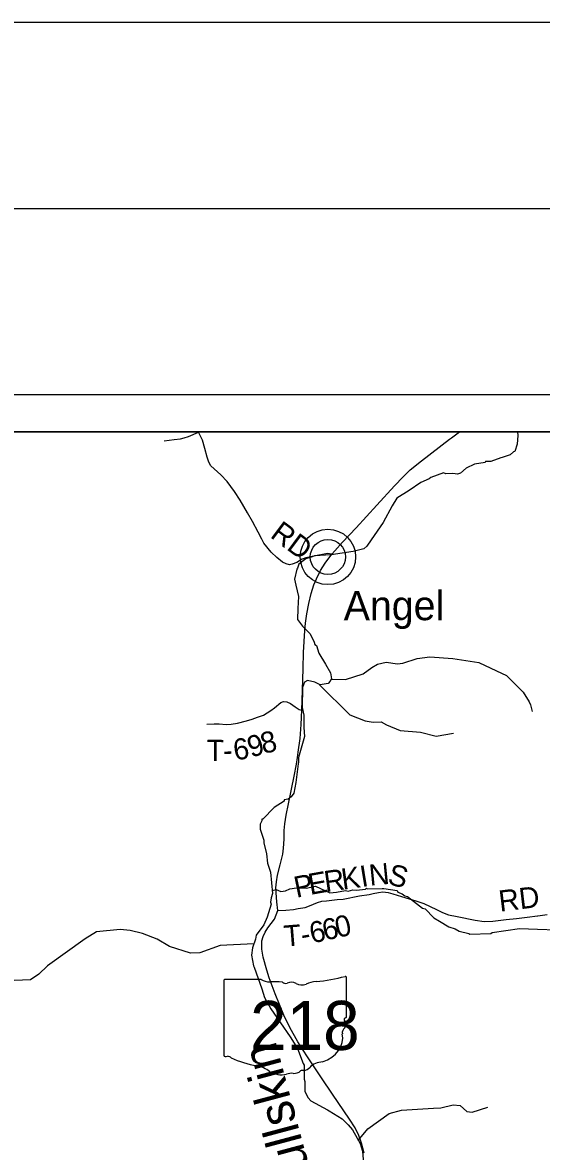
# Model space of a CAD drawing. Extents: x -1.8 to 75.7, y -2 to 25.
# Drawn here: x 46.551 to 47.944, y 20.577 to 23.612 of the extents above; entities that cross this region are included whole.
import ezdxf

# ---------------------------------------------------------------- set-up
doc = ezdxf.new("R2010")
doc.units = 0
for name, color, linetype in [('GM_X_County_Road', 7, 'Continuous'), ('GM_X_County_Road_Text', 7, 'Continuous'), ('GM_X_Minor_River', 7, 'Continuous'), ('GM_X_Minor_River_Text', 7, 'Continuous'), ('GM_X_State_Location', 7, 'Continuous'), ('GM_X_State_Route', 7, 'Continuous'), ('GM_X_State_Shield', 7, 'Continuous'), ('GM_X_Township', 7, 'Continuous'), ('GM_X_Township_Road', 7, 'Continuous'), ('GM_X_Township_Road_Text', 7, 'Continuous'), ('GM_X_Unincorporated', 7, 'Continuous'), ('GM_X_Unincorporated_Location', 7, 'Continuous'), ('GM_X_Unincorporated_Text', 7, 'Continuous'), ('SH_Border', 7, 'Continuous'), ('SH_Cut_Line', 7, 'Continuous'), ('SH_Data', 7, 'Continuous')]:
    doc.layers.add(name, color=color, linetype=linetype)

msp = doc.modelspace()

# ---------------------------------------------------------------- linework, layer by layer
at = {"layer": 'GM_X_County_Road'}
msp.add_lwpolyline([(47.3812, 22.183), (47.3696, 22.185), (47.3328, 22.1778), (47.311, 22.1729), (47.301, 22.1692), (47.2869, 22.1609), (47.2746, 22.156), (47.2669, 22.1545), (47.2588, 22.1566), (47.2482, 22.1614), (47.2333, 22.1738), (47.2178, 22.1881), (47.1983, 22.2125), (47.1926, 22.2231), (47.1834, 22.2418), (47.1676, 22.271), (47.1547, 22.2943), (47.1346, 22.3278), (47.1194, 22.3516), (47.0996, 22.3783), (47.083, 22.3964), (47.0646, 22.4124), (47.056, 22.4205), (47.0508, 22.4299), (47.046, 22.4434), (47.0397, 22.4672), (47.0336, 22.489), (47.0233, 22.5108), (47.0227, 22.5121)], dxfattribs=at)
at = {"layer": 'GM_X_Minor_River'}
for points in [[(47.8797, 22.5121), (47.8808, 22.502), (47.8785, 22.4788), (47.8729, 22.4587), (47.8687, 22.4583), (47.86, 22.4503), (47.8385, 22.443), (47.8347, 22.4422), (47.8079, 22.4319), (47.7935, 22.4322), (47.7931, 22.4296), (47.7644, 22.4253), (47.7417, 22.4139), (47.7266, 22.4009), (47.7187, 22.3979), (47.7062, 22.3997), (47.6873, 22.3989), (47.6813, 22.4012), (47.6469, 22.3893), (47.642, 22.3859), (47.62, 22.376), (47.5883, 22.3542), (47.5558, 22.3336), (47.543, 22.3131), (47.5192, 22.2682), (47.4871, 22.2213), (47.4754, 22.2042), (47.4671, 22.1973), (47.4384, 22.1897), (47.3794, 22.1816), (47.3348, 22.1788), (47.3284, 22.1761), (47.311, 22.17), (47.2925, 22.1563), (47.2887, 22.1456), (47.2872, 22.1426), (47.2808, 22.1156), (47.2846, 22.0992), (47.2911, 22.0692), (47.2896, 22.0369), (47.2892, 22.0069), (47.3025, 21.9894), (47.3225, 21.9689), (47.3339, 21.9462), (47.3354, 21.9401), (47.3396, 21.9378), (47.3464, 21.9166), (47.3642, 21.8873), (47.3778, 21.8638), (47.3801, 21.8482), (47.3775, 21.844), (47.3763, 21.8417), (47.3711, 21.8349), (47.3495, 21.8314), (47.3355, 21.8386), (47.3155, 21.8435), (47.3075, 21.8389), (47.3026, 21.8241), (47.3012, 21.7705), (47.3057, 21.75), (47.3058, 21.7173), (47.3073, 21.6926), (47.3043, 21.6804), (47.2911, 21.6367), (47.2915, 21.6234), (47.2904, 21.6196), (47.2844, 21.569), (47.2791, 21.5401), (47.2715, 21.5309), (47.264, 21.5241), (47.2534, 21.5222), (47.253, 21.5191), (47.2262, 21.502), (47.196, 21.4707), (47.1926, 21.4703), (47.1926, 21.4661), (47.1888, 21.4574), (47.1885, 21.4437), (47.1983, 21.4145), (47.198, 21.4072), (47.2059, 21.3772), (47.2086, 21.3522), (47.2162, 21.3278), (47.2215, 21.2708), (47.2181, 21.2594), (47.2159, 21.2473), (47.2178, 21.2419), (47.2076, 21.2073), (47.1982, 21.1864), (47.1782, 21.159)], [(47.379, 21.8471), (47.4179, 21.8458), (47.4656, 21.8614), (47.4884, 21.8785), (47.5038, 21.8875), (47.5267, 21.8929), (47.5575, 21.8881), (47.5715, 21.8895), (47.6105, 21.9027), (47.6443, 21.9066), (47.7057, 21.9027), (47.7757, 21.8914), (47.8234, 21.8697), (47.8503, 21.8567), (47.895, 21.8124), (47.9109, 21.786), (47.9148, 21.7783), (47.9188, 21.7596)], [(47.3483, 21.832), (47.4298, 21.751), (47.4709, 21.7349), (47.492, 21.7312), (47.5139, 21.732), (47.528, 21.7243), (47.5646, 21.7087), (47.6193, 21.7043), (47.6613, 21.6939), (47.7077, 21.7015)], [(47.2207, 21.2792), (47.2313, 21.2811), (47.2438, 21.2762), (47.2563, 21.2778), (47.268, 21.2831), (47.2862, 21.2862), (47.3119, 21.2847), (47.3368, 21.2901), (47.3758, 21.2727), (47.3939, 21.2747), (47.4173, 21.2789), (47.4249, 21.277), (47.437, 21.2808), (47.4476, 21.2797), (47.4714, 21.2824), (47.4744, 21.2851), (47.4763, 21.2828), (47.5164, 21.2837), (47.5209, 21.2841), (47.5568, 21.2788), (47.558, 21.2747), (47.5701, 21.2701), (47.5769, 21.2641), (47.5844, 21.2629), (47.6249, 21.2315), (47.6313, 21.2296), (47.6548, 21.2053), (47.6699, 21.1959), (47.6949, 21.1807), (47.7123, 21.1758), (47.7233, 21.1694), (47.7493, 21.163), (47.7516, 21.1615), (47.8076, 21.1635), (47.8113, 21.1662), (47.8847, 21.177), (47.9334, 21.1752), (47.9845, 21.1734)], [(47.1715, 21.1353), (47.0815, 21.1308), (47.0262, 21.1108), (47.0011, 21.1099), (46.9449, 21.1286), (46.9121, 21.1478), (46.8729, 21.1635), (46.8395, 21.1713), (46.8129, 21.1735), (46.7492, 21.1678), (46.7182, 21.149), (46.6173, 21.0764), (46.5939, 21.0542), (46.5716, 21.0389), (46.5287, 21.0368), (46.4638, 21.0418), (46.407, 21.0156), (46.3964, 21.0107), (46.3945, 21.0103)], [(47.1782, 21.159), (47.1759, 21.148), (47.1676, 21.1244), (47.165, 21.105), (47.1711, 21.0765), (47.1722, 21.0723), (47.193, 21.0146), (47.2003, 20.991), (47.2169, 20.9606), (47.2695, 20.8851), (47.2892, 20.8544), (47.3044, 20.8141), (47.307, 20.8092), (47.3071, 20.7715), (47.3083, 20.7651)], [(47.3083, 20.7654), (47.3086, 20.7385), (47.3173, 20.7214), (47.3249, 20.713), (47.3695, 20.6888), (47.3737, 20.6862), (47.4092, 20.6653), (47.4251, 20.649), (47.4365, 20.635), (47.4569, 20.5986), (47.4634, 20.5784), (47.4676, 20.5233)], [(47.4521, 20.6071), (47.4776, 20.6378), (47.5348, 20.6793), (47.568, 20.6885), (47.6543, 20.6937), (47.674, 20.6946), (47.7067, 20.7027), (47.7256, 20.7006), (47.7436, 20.6848), (47.7575, 20.6828), (47.8003, 20.6963)]]:
    msp.add_lwpolyline(points, dxfattribs=at)
at = {"layer": 'GM_X_State_Route'}
for points in [[(47.3812, 22.183), (47.3894, 22.192), (47.4101, 22.2148), (47.4463, 22.2535), (47.5022, 22.3146), (47.5497, 22.3663), (47.5725, 22.3908), (47.5916, 22.41), (47.6216, 22.4343), (47.6972, 22.4917), (47.7025, 22.4956)], [(47.7025, 22.4956), (47.7242, 22.5121)], [(47.2886, 21.6363), (47.291, 21.6508), (47.2961, 21.6878), (47.2987, 21.7248), (47.3004, 21.7638), (47.3019, 21.8175), (47.3041, 21.876), (47.3053, 21.919), (47.3082, 21.9775), (47.3107, 21.9971), (47.3139, 22.0229), (47.3191, 22.0504), (47.3251, 22.0774), (47.3328, 22.1003), (47.34, 22.1164), (47.3509, 22.1391), (47.3635, 22.1589), (47.3812, 22.183)], [(47.4679, 20.5727), (47.4604, 20.5999), (47.4531, 20.6198), (47.4436, 20.6405), (47.4285, 20.6643), (47.3829, 20.7309), (47.3535, 20.7748), (47.3138, 20.8341), (47.2893, 20.8722), (47.2679, 20.9107), (47.2521, 20.9435), (47.2288, 21.0008), (47.2125, 21.0441), (47.2062, 21.0643), (47.1967, 21.0995), (47.1928, 21.1214), (47.1931, 21.1432), (47.1965, 21.1554), (47.2016, 21.1671), (47.2089, 21.1782), (47.2271, 21.2018), (47.2319, 21.2132), (47.2356, 21.2254), (47.2336, 21.2486), (47.2313, 21.2721), (47.231, 21.2859), (47.2321, 21.3023), (47.2353, 21.32), (47.2422, 21.3476), (47.2491, 21.3766), (47.2511, 21.3929), (47.2528, 21.4167), (47.2531, 21.4402), (47.2548, 21.4583), (47.2588, 21.4813), (47.2648, 21.5117), (47.2798, 21.5863), (47.2858, 21.6187), (47.2886, 21.6363)]]:
    msp.add_lwpolyline(points, dxfattribs=at)
at = {"layer": 'GM_X_State_Shield'}
for p, q in [((47.0912, 21.0362), (47.0912, 20.8361)), ((47.1909, 21.0396), (47.0944, 21.0396)), ((47.4208, 20.9399), (47.4208, 21.0446)), ((47.4207, 20.9399), (47.4208, 20.9399))]:
    msp.add_line(p, q, dxfattribs=at)
for centre, major_axis, start_param, end_param in [((47.0949, 21.0366), (0.00382, 0), 1.712693, 3.28349), ((47.2139, 21.0628), (0.037, 0), 4.042523, 4.731795), ((47.2262, 20.9273), (0.133, 0), 1.404758, 1.657858), ((47.2564, 21.0376), (0.0107, 0), 3.836095, 5.185415), ((47.2721, 21.0145), (0.0222, 0), 0.950623, 2.079405), ((47.3479, 20.9785), (0.0703, 0), 1.699011, 2.107814), ((47.3034, 21.3124), (0.3495, 0), 4.814394, 5.042369), ((47.4171, 21.045), (0.00367, 0), 6.141152, 7.989035), ((47.3007, 21.0462), (0.0267, 0), 4.081561, 5.145723), ((47.4339, 20.8961), (0.0248, 0), 2.387724, 3.262537), ((47.4199, 20.9322), (0.00568, 0), 1.883978, 3.671073), ((47.3838, 20.919), (0.0341, 0), 5.934695, 6.695948), ((47.4168, 20.9395), (0.00393, 0), 5.05454, 6.418171), ((47.3229, 20.8828), (0.0874, 0), 5.101752, 6.440018), ((47.095, 20.8356), (0.00385, 0), 3.00124, 4.508301), ((47.0956, 20.8561), (0.0294, 0), 4.665946, 4.897461), ((47.1016, 20.8245), (0.0106, 0), 0.519207, 1.627899), ((47.2354, 21.0043), (0.2524, 0), 4.195997, 4.488961), ((47.1602, 20.7461), (0.079, 0), 0.823519, 1.323587), ((47.2456, 20.8235), (0.0501, 0), 4.026481, 4.996735), ((47.2782, 20.8085), (0.0267, 0), 4.691044, 5.507374), ((47.3023, 20.7891), (0.00752, 0), 1.147584, 2.315152), ((47.2991, 20.8167), (0.0282, 0), 4.937069, 5.64225), ((47.3598, 20.7799), (0.0479, 0), 1.647645, 2.488434), ((47.2745, 20.7543), (0.0412, 0), 1.495662, 1.94098)]:
    msp.add_ellipse(centre, major_axis=major_axis, ratio=0.8, start_param=start_param, end_param=end_param, dxfattribs=at)
at = {"layer": 'GM_X_Township'}
msp.add_lwpolyline([(48.1876, 22.5121), (43.8002, 22.5121), (43.8002, 18.978)], dxfattribs=at)
at = {"layer": 'GM_X_Township_Road'}
for points in [[(46.9304, 22.4873), (46.9579, 22.491), (46.9742, 22.4933), (46.9846, 22.4954), (46.9958, 22.4991), (47.0233, 22.5108)], [(47.0451, 21.726), (47.0649, 21.7265), (47.0781, 21.7268), (47.0973, 21.7254), (47.1105, 21.726), (47.1274, 21.7283), (47.1521, 21.7346), (47.1667, 21.7392), (47.1817, 21.7446), (47.1977, 21.7503), (47.2172, 21.763), (47.2267, 21.7701), (47.2445, 21.7842), (47.2516, 21.7868), (47.2603, 21.7859), (47.2697, 21.7816), (47.2829, 21.7721), (47.293, 21.765), (47.3004, 21.7638)], [(47.2356, 21.2254), (47.2575, 21.226), (47.2779, 21.2279), (47.2907, 21.2302), (47.3093, 21.2329), (47.3214, 21.2374), (47.3426, 21.2463), (47.3541, 21.2505), (47.3669, 21.2514), (47.3954, 21.2544), (47.4116, 21.2553), (47.4551, 21.2642), (47.4817, 21.2681), (47.4923, 21.2704), (47.5065, 21.2737), (47.5182, 21.2754), (47.5319, 21.2734), (47.5453, 21.2698), (47.5802, 21.2589), (47.6062, 21.2508), (47.628, 21.2438), (47.6617, 21.2274), (47.6779, 21.2193), (47.6944, 21.2134), (47.7173, 21.2089), (47.7664, 21.1994), (47.7899, 21.1958), (47.8133, 21.1964), (47.8491, 21.2008), (47.8767, 21.2036), (47.9052, 21.2073), (47.933, 21.2107)], [(47.933, 21.2107), (47.9345, 21.2109), (47.9597, 21.2138)]]:
    msp.add_lwpolyline(points, dxfattribs=at)
at = {"layer": 'GM_X_Unincorporated'}
for radius in [0.0744, 0.0472]:
    msp.add_circle((47.3704, 22.1756), radius, dxfattribs=at)
at = {"layer": 'GM_X_Unincorporated_Location'}
msp.add_line((47.3704, 22.1756), (47.3704, 22.1756), dxfattribs=at)
at = {"layer": 'SH_Border'}
msp.add_lwpolyline([(43.2002, 23.1121), (75.2002, 23.1121), (75.2002, 2.1121), (43.2002, 2.1121)], close=True, dxfattribs=at)
at = {"layer": 'SH_Cut_Line'}
msp.add_lwpolyline([(41.7002, 1.6121), (75.7002, 1.6121), (75.7002, 23.6121), (41.7002, 23.6121)], close=True, dxfattribs=at)
at = {"layer": 'SH_Data'}
for p, q in [((43.7002, 22.6121), (50.7002, 22.6121)), ((43.8002, 22.5121), (50.6002, 22.5121)), ((43.8002, 22.5121), (50.6002, 22.5121))]:
    msp.add_line(p, q, dxfattribs=at)

# ---------------------------------------------------------------- texts
at = {"layer": 'GM_X_County_Road_Text'}
msp.add_text('RD', height=0.05682, rotation=323.3346, dxfattribs=at).set_placement((47.2129, 22.23))
at = {"layer": 'GM_X_Minor_River_Text'}
msp.add_text('Bullskin', height=0.09471, rotation=105.0011, dxfattribs=at).set_placement((47.3421, 20.4554))
at = {"layer": 'GM_X_State_Location'}
for s in ['s', 'r']:
    msp.add_text(s, height=0.000189, dxfattribs=at).set_placement((47.2523, 20.9228))
msp.add_text('218', height=0.000189, rotation=0, dxfattribs=at).set_placement((47.1854, 20.909))
at = {"layer": 'GM_X_State_Shield'}
msp.add_text('218', height=0.13184, dxfattribs=at).set_placement((47.1615, 20.8502))
at = {"layer": 'GM_X_Township_Road_Text'}
for s, height, rotation, p in [('9', 0.0568, 17.1355, (47.1642, 21.6355)), ('8', 0.0568, 13.135, (47.1967, 21.6455)), ('T', 0.0568, 359.1664, (47.0446, 21.6276)), ('6', 0.0568, 8.491, (47.1205, 21.6283)), ('-', 0.0568, 1.4176, (47.0896, 21.627)), ('R', 0.0568, 8.1475, (47.3642, 21.2741)), ('K', 0.0568, 7.8733, (47.4103, 21.2807)), ('I', 0.0568, 9.3449, (47.4614, 21.2878)), ('N', 0.0568, 5.6243, (47.4835, 21.2914)), ('S', 0.0568, 345.3323, (47.528, 21.2968)), ('P', 0.0568, 11.7297, (47.2858, 21.2589)), ('E', 0.0568, 10.1916, (47.3229, 21.2667)), ('RD', 0.05682, 6.8826, (47.8326, 21.2217)), ('0', 0.0568, 12.4732, (47.3963, 21.1511)), ('T', 0.0568, 4.5907, (47.2541, 21.1277)), ('6', 0.0568, 11.9572, (47.3273, 21.1362)), ('6', 0.0568, 12.3763, (47.362, 21.1436)), ('-', 0.0568, 9.9309, (47.3022, 21.1318))]:
    msp.add_text(s, height=height, rotation=rotation, dxfattribs=at).set_placement(p)
at = {"layer": 'GM_X_Unincorporated_Text'}
msp.add_text('Angel', height=0.07898, rotation=0, dxfattribs=at).set_placement((47.4129, 22.0054))

doc.saveas('drawing.dxf')
